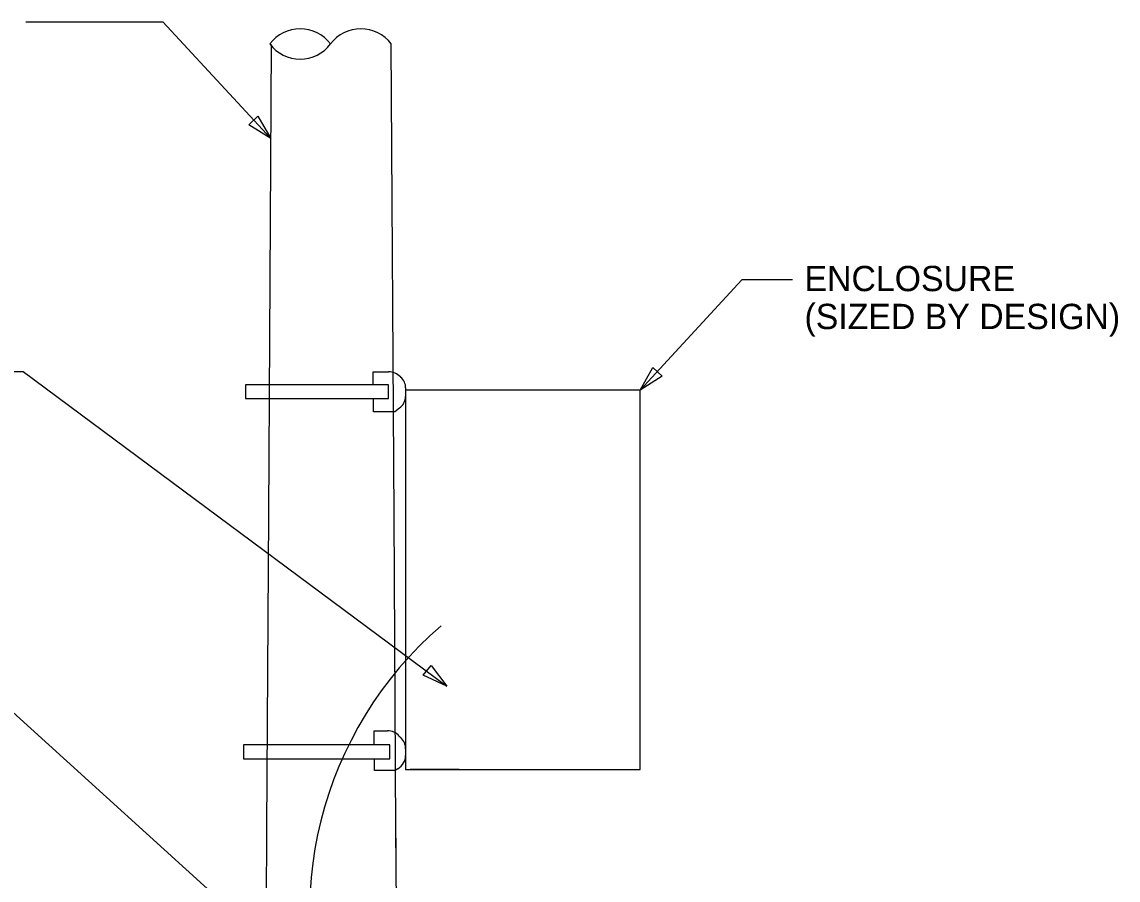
# Model space of a CAD drawing. Extents: x 1299104.8 to 1299141.6, y 239639.8 to 239661.8.
# Drawn here: x 1299110.16 to 1299115.36, y 239652.36 to 239656.43 of the extents above; entities that cross this region are included whole.
import ezdxf

# ---------------------------------------------------------------- set-up
doc = ezdxf.new("R2010")
doc.units = 0
doc.layers.add('DIM TXT', color=7, linetype='Continuous')

msp = doc.modelspace()

# ---------------------------------------------------------------- linework, layer by layer
at = {"layer": 'DIM TXT'}
for p, q in [((1299111.3306, 239654.0922), (1299111.3439, 239656.3219)), ((1299111.9253, 239654.0887), (1299111.912, 239656.3253)), ((1299111.9555, 239654.7449), (1299111.9567, 239654.7436)), ((1299111.8995, 239654.7077), (1299111.2209, 239654.7077)), ((1299111.2209, 239654.7077), (1299111.2209, 239654.6429)), ((1299111.8995, 239654.6429), (1299111.8995, 239654.7077)), ((1299111.9806, 239654.6938), (1299111.9806, 239654.6516)), ((1299111.2209, 239654.6429), (1299111.8995, 239654.6429)), ((1299111.3218, 239652.6029), (1299111.3306, 239654.0922)), ((1299111.9342, 239652.5992), (1299111.9253, 239654.0887)), ((1299111.9504, 239653.0406), (1299111.957, 239653.0334)), ((1299111.9806, 239652.9803), (1299111.9806, 239652.9486)), ((1299112.2343, 239652.8822), (1299112.0019, 239652.8822)), ((1299111.3155, 239651.5455), (1299111.3218, 239652.6029)), ((1299111.9405, 239651.5455), (1299111.9342, 239652.5992)), ((1299111.9356, 239652.3577), (1299111.9356, 239652.5561))]:
    msp.add_line(p, q, dxfattribs=at)
for points in [[(1299110.1785, 239656.4298), (1299110.8277, 239656.4298), (1299111.3412, 239655.8758)], [(1299113.8162, 239655.2062), (1299113.5762, 239655.2062), (1299113.0935, 239654.6815)], [(1299112.1765, 239653.2764), (1299110.1659, 239654.7692), (1299109.5805, 239654.7692)], [(1299111.8269, 239654.7077), (1299111.8269, 239654.769), (1299111.8999, 239654.769)], [(1299111.9506, 239654.5972), (1299111.93, 239654.5792), (1299111.8284, 239654.5792), (1299111.8284, 239654.6429)], [(1299111.4841, 239651.9115), (1299109.8244, 239653.4184), (1299109.6414, 239653.4184)], [(1299111.8306, 239652.998), (1299111.8306, 239653.0653), (1299111.8942, 239653.0653)], [(1299111.9435, 239652.8857), (1299111.9307, 239652.877), (1299111.8321, 239652.877), (1299111.832, 239652.9321)]]:
    msp.add_lwpolyline(points, dxfattribs=at)
for points in [[(1299111.2797, 239655.9831), (1299111.3412, 239655.8758), (1299111.2365, 239655.9415)], [(1299113.1969, 239654.7493), (1299113.0935, 239654.6815), (1299113.1529, 239654.79)], [(1299113.0935, 239654.6815), (1299111.9806, 239654.6815), (1299111.9806, 239652.8822), (1299113.0935, 239652.8822)], [(1299112.1014, 239653.3756), (1299112.1758, 239653.2768), (1299112.0637, 239653.3289)], [(1299111.9056, 239652.9984), (1299111.2104, 239652.9984), (1299111.2104, 239652.9321), (1299111.9056, 239652.9321)]]:
    msp.add_lwpolyline(points, close=True, dxfattribs=at)
for centre, radius, start, end in [((1299111.4801, 239656.2173), 0.18, 36.8699, 143.1301), ((1299111.768, 239656.2173), 0.18, 36.8699, 143.1301), ((1299111.4801, 239656.4332), 0.18, 216.8699, 323.1301), ((1299111.8999, 239654.6927), 0.0763, 43.1524, 90), ((1299113.3259, 239652.1998), 1.802, 130.7832, 201.0742), ((1299111.8942, 239652.989), 0.0763, 42.5104, 90)]:
    msp.add_arc(centre, radius, start, end, dxfattribs=at)
for centre, major_axis, ratio, start_param, end_param in [((1299111.8923, 239654.6948), (0.0883, 0), 0.807957, 6.26848, 7.036337), ((1299111.8932, 239654.6526), (0.0873, 0), 0.841662, 5.428931, 6.26848), ((1299111.8908, 239652.9803), (0.0898, 0), 0.874496, 6.283185, 7.025133), ((1299111.8962, 239652.9486), (0.0844, 0), 0.9011, 5.307799, 6.283185)]:
    msp.add_ellipse(centre, major_axis=major_axis, ratio=ratio, start_param=start_param, end_param=end_param, dxfattribs=at)

# ---------------------------------------------------------------- texts
for s, p in [('ENCLOSURE', (1299113.8729, 239655.152)), ('(SIZED BY DESIGN)', (1299113.8729, 239654.972))]:
    msp.add_text(s, height=0.12, dxfattribs=at).set_placement(p)

doc.saveas('drawing.dxf')
